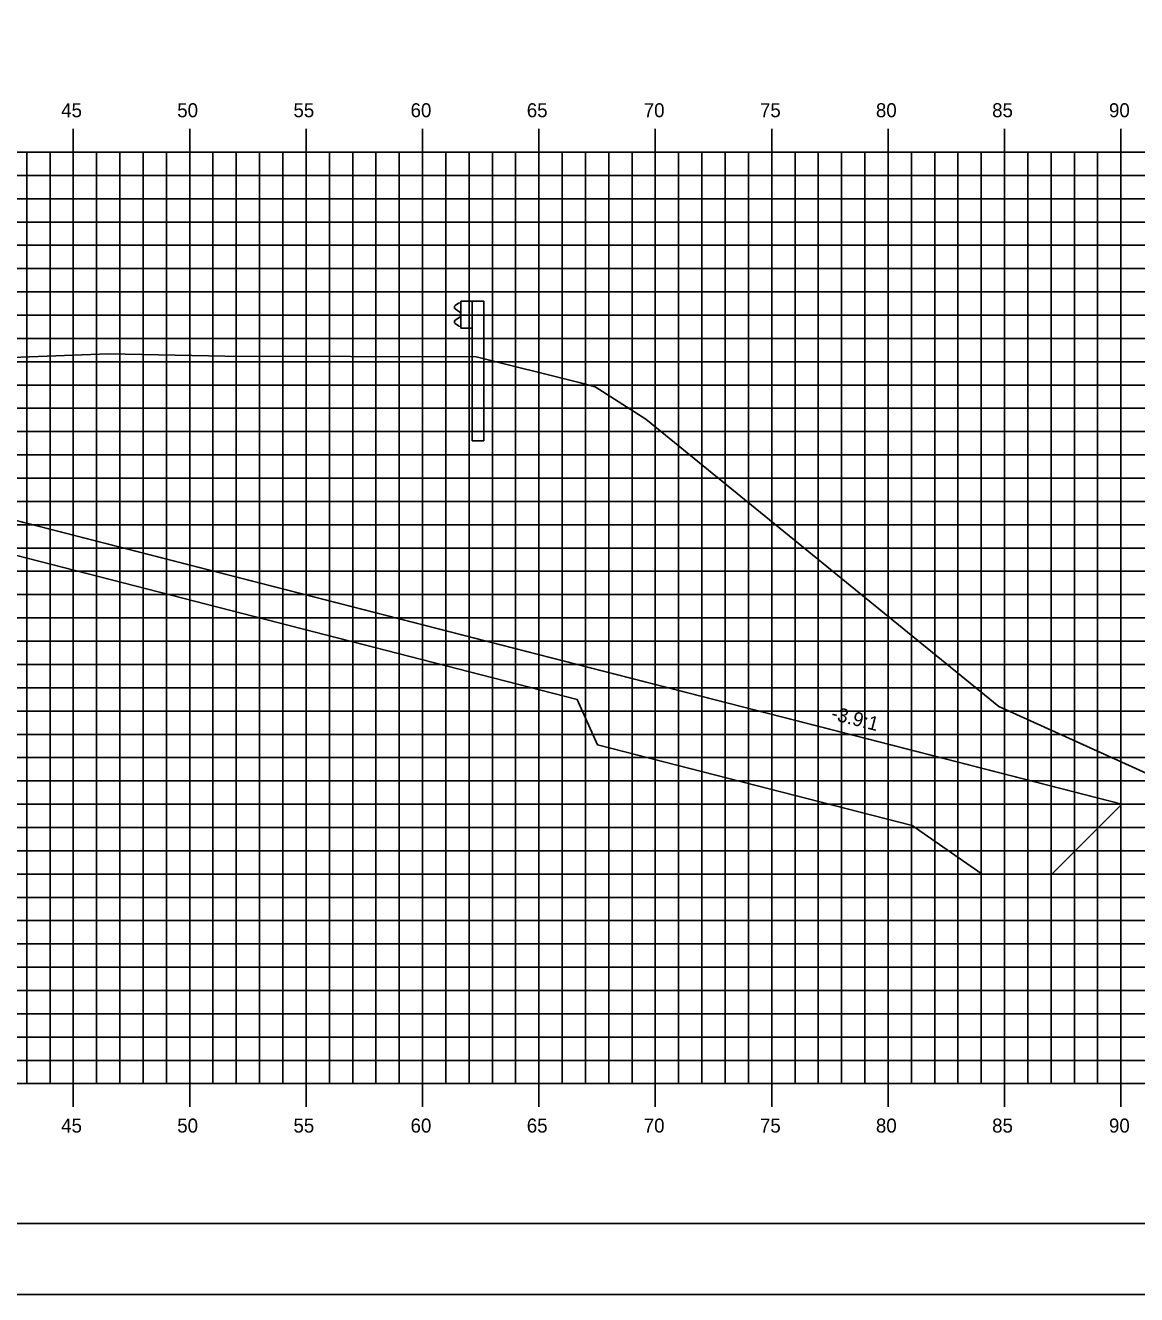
# Model space of a CAD drawing. Extents: x 850598 to 870284, y 366541 to 366651.
# Drawn here: x 853354.9 to 853402.6, y 366541.2 to 366595.7 of the extents above; entities that cross this region are included whole.
import ezdxf

# ---------------------------------------------------------------- set-up
doc = ezdxf.new("R2010")
doc.units = 0
for name, color, linetype in [('ANNOTATION', 7, 'Continuous'), ('BORDER', 7, 'Continuous'), ('D_Drainage_RipRap', 7, 'Continuous'), ('D_Roadway_Centerline', 7, 'Continuous'), ('D_Roadway_SlopeLines', 7, 'Continuous'), ('H_V ANNOTATION', 7, 'Continuous'), ('MAJOR', 7, 'Continuous'), ('MINOR', 7, 'Continuous'), ('PLOT BOUNDARY', 7, 'Continuous'), ('S_Guardrail_Beam', 7, 'Continuous'), ('S_Roadway_Centerline', 7, 'Continuous')]:
    doc.layers.add(name, color=color, linetype=linetype)

msp = doc.modelspace()

# ---------------------------------------------------------------- linework, layer by layer
at = {"layer": 'BORDER'}
msp.add_line((853266.976, 366544.225), (853426.976, 366544.225), dxfattribs=at)
at = {"layer": 'D_Drainage_RipRap'}
msp.add_lwpolyline([(853378.624, 366568.225), (853392.147, 366564.756), (853402.009, 366562.225), (853399.009, 366559.225), (853396.009, 366559.225), (853393.009, 366561.306), (853379.486, 366564.775), (853378.624, 366566.725), (853334.975, 366577.924), (853334.975, 366579.424)], close=True, dxfattribs=at)
at = {"layer": 'D_Roadway_Centerline'}
msp.add_lwpolyline([(853275.109, 366582.924), (853276.109, 366582.958), (853277.109, 366582.839), (853278.109, 366582.568), (853286.975, 366578.211), (853290.778, 366579.478), (853296.975, 366581.544), (853300.975, 366581.784), (853311.975, 366582.114), (853322.975, 366581.784), (853326.975, 366581.544), (853328.975, 366581.424), (853334.975, 366579.424), (853378.624, 366568.225), (853392.147, 366564.756), (853402.009, 366562.225), (853406.009, 366562.225)], dxfattribs=at)
at = {"layer": 'D_Roadway_SlopeLines'}
msp.add_lwpolyline([(853334.975, 366579.424), (853402.009, 366562.225), (853402.009, 366562.225)], dxfattribs=at)
at = {"layer": 'MAJOR'}
for p, q in [((853356.975, 366591.227), (853356.975, 366590.225)), ((853356.975, 366591.227), (853356.975, 366590.225)), ((853361.975, 366591.227), (853361.975, 366590.225)), ((853361.975, 366591.227), (853361.975, 366590.225)), ((853366.975, 366591.227), (853366.975, 366590.225)), ((853366.975, 366591.227), (853366.975, 366590.225)), ((853371.975, 366591.227), (853371.975, 366590.225)), ((853371.975, 366591.227), (853371.975, 366590.225)), ((853376.975, 366591.227), (853376.975, 366590.225)), ((853376.975, 366591.227), (853376.975, 366590.225)), ((853381.975, 366591.227), (853381.975, 366590.225)), ((853381.975, 366591.227), (853381.975, 366590.225)), ((853386.975, 366591.227), (853386.975, 366590.225)), ((853386.975, 366591.227), (853386.975, 366590.225)), ((853391.975, 366591.227), (853391.975, 366590.225)), ((853391.975, 366591.227), (853391.975, 366590.225)), ((853396.975, 366591.227), (853396.975, 366590.225)), ((853396.975, 366591.227), (853396.975, 366590.225)), ((853401.975, 366591.227), (853401.975, 366590.225)), ((853401.975, 366591.227), (853401.975, 366590.225)), ((853271.975, 366590.225), (853411.975, 366590.225)), ((853271.975, 366590.225), (853411.975, 366590.225)), ((853271.975, 366590.225), (853411.975, 366590.225)), ((853271.975, 366590.225), (853411.975, 366590.225)), ((853356.975, 366550.225), (853356.975, 366590.225)), ((853356.975, 366550.225), (853356.975, 366590.225)), ((853361.975, 366550.225), (853361.975, 366590.225)), ((853361.975, 366550.225), (853361.975, 366590.225)), ((853366.975, 366550.225), (853366.975, 366590.225)), ((853366.975, 366550.225), (853366.975, 366590.225)), ((853371.975, 366550.225), (853371.975, 366590.225)), ((853371.975, 366550.225), (853371.975, 366590.225)), ((853376.975, 366550.225), (853376.975, 366590.225)), ((853376.975, 366550.225), (853376.975, 366590.225)), ((853381.975, 366550.225), (853381.975, 366590.225)), ((853381.975, 366550.225), (853381.975, 366590.225)), ((853386.975, 366550.225), (853386.975, 366590.225)), ((853386.975, 366550.225), (853386.975, 366590.225)), ((853391.975, 366550.225), (853391.975, 366590.225)), ((853391.975, 366550.225), (853391.975, 366590.225)), ((853396.975, 366550.225), (853396.975, 366590.225)), ((853396.975, 366550.225), (853396.975, 366590.225)), ((853401.975, 366550.225), (853401.975, 366590.225)), ((853401.975, 366550.225), (853401.975, 366590.225)), ((853271.975, 366585.225), (853411.975, 366585.225)), ((853271.975, 366585.225), (853411.975, 366585.225)), ((853271.975, 366580.225), (853411.975, 366580.225)), ((853271.975, 366580.225), (853411.975, 366580.225)), ((853271.975, 366575.225), (853411.975, 366575.225)), ((853271.975, 366575.225), (853411.975, 366575.225)), ((853271.975, 366570.225), (853411.975, 366570.225)), ((853271.975, 366570.225), (853411.975, 366570.225)), ((853271.975, 366565.225), (853411.975, 366565.225)), ((853271.975, 366565.225), (853411.975, 366565.225)), ((853271.975, 366560.225), (853411.975, 366560.225)), ((853271.975, 366560.225), (853411.975, 366560.225)), ((853271.975, 366555.225), (853411.975, 366555.225)), ((853271.975, 366555.225), (853411.975, 366555.225)), ((853271.975, 366550.225), (853411.975, 366550.225)), ((853271.975, 366550.225), (853411.975, 366550.225)), ((853271.975, 366550.225), (853411.975, 366550.225)), ((853271.975, 366550.225), (853411.975, 366550.225)), ((853356.975, 366549.223), (853356.975, 366550.225)), ((853356.975, 366549.223), (853356.975, 366550.225)), ((853361.975, 366549.223), (853361.975, 366550.225)), ((853361.975, 366549.223), (853361.975, 366550.225)), ((853366.975, 366549.223), (853366.975, 366550.225)), ((853366.975, 366549.223), (853366.975, 366550.225)), ((853371.975, 366549.223), (853371.975, 366550.225)), ((853371.975, 366549.223), (853371.975, 366550.225)), ((853376.975, 366549.223), (853376.975, 366550.225)), ((853376.975, 366549.223), (853376.975, 366550.225)), ((853381.975, 366549.223), (853381.975, 366550.225)), ((853381.975, 366549.223), (853381.975, 366550.225)), ((853386.975, 366549.223), (853386.975, 366550.225)), ((853386.975, 366549.223), (853386.975, 366550.225)), ((853391.975, 366549.223), (853391.975, 366550.225)), ((853391.975, 366549.223), (853391.975, 366550.225)), ((853396.975, 366549.223), (853396.975, 366550.225)), ((853396.975, 366549.223), (853396.975, 366550.225)), ((853401.975, 366549.223), (853401.975, 366550.225)), ((853401.975, 366549.223), (853401.975, 366550.225))]:
    msp.add_line(p, q, dxfattribs=at)
at = {"layer": 'MINOR'}
for p, q in [((853354.975, 366550.225), (853354.975, 366590.225)), ((853354.975, 366550.225), (853354.975, 366590.225)), ((853355.975, 366550.225), (853355.975, 366590.225)), ((853355.975, 366550.225), (853355.975, 366590.225)), ((853357.975, 366550.225), (853357.975, 366590.225)), ((853357.975, 366550.225), (853357.975, 366590.225)), ((853358.975, 366550.225), (853358.975, 366590.225)), ((853358.975, 366550.225), (853358.975, 366590.225)), ((853359.975, 366550.225), (853359.975, 366590.225)), ((853359.975, 366550.225), (853359.975, 366590.225)), ((853360.975, 366550.225), (853360.975, 366590.225)), ((853360.975, 366550.225), (853360.975, 366590.225)), ((853362.975, 366550.225), (853362.975, 366590.225)), ((853362.975, 366550.225), (853362.975, 366590.225)), ((853363.975, 366550.225), (853363.975, 366590.225)), ((853363.975, 366550.225), (853363.975, 366590.225)), ((853364.975, 366550.225), (853364.975, 366590.225)), ((853364.975, 366550.225), (853364.975, 366590.225)), ((853365.975, 366550.225), (853365.975, 366590.225)), ((853365.975, 366550.225), (853365.975, 366590.225)), ((853367.975, 366550.225), (853367.975, 366590.225)), ((853367.975, 366550.225), (853367.975, 366590.225)), ((853368.975, 366550.225), (853368.975, 366590.225)), ((853368.975, 366550.225), (853368.975, 366590.225)), ((853369.975, 366550.225), (853369.975, 366590.225)), ((853369.975, 366550.225), (853369.975, 366590.225)), ((853370.975, 366550.225), (853370.975, 366590.225)), ((853370.975, 366550.225), (853370.975, 366590.225)), ((853372.975, 366550.225), (853372.975, 366590.225)), ((853372.975, 366550.225), (853372.975, 366590.225)), ((853373.975, 366550.225), (853373.975, 366590.225)), ((853373.975, 366550.225), (853373.975, 366590.225)), ((853374.975, 366550.225), (853374.975, 366590.225)), ((853374.975, 366550.225), (853374.975, 366590.225)), ((853375.975, 366550.225), (853375.975, 366590.225)), ((853375.975, 366550.225), (853375.975, 366590.225)), ((853377.975, 366550.225), (853377.975, 366590.225)), ((853377.975, 366550.225), (853377.975, 366590.225)), ((853378.975, 366550.225), (853378.975, 366590.225)), ((853378.975, 366550.225), (853378.975, 366590.225)), ((853379.975, 366550.225), (853379.975, 366590.225)), ((853379.975, 366550.225), (853379.975, 366590.225)), ((853380.975, 366550.225), (853380.975, 366590.225)), ((853380.975, 366550.225), (853380.975, 366590.225)), ((853382.975, 366550.225), (853382.975, 366590.225)), ((853382.975, 366550.225), (853382.975, 366590.225)), ((853383.975, 366550.225), (853383.975, 366590.225)), ((853383.975, 366550.225), (853383.975, 366590.225)), ((853384.975, 366550.225), (853384.975, 366590.225)), ((853384.975, 366550.225), (853384.975, 366590.225)), ((853385.975, 366550.225), (853385.975, 366590.225)), ((853385.975, 366550.225), (853385.975, 366590.225)), ((853387.975, 366550.225), (853387.975, 366590.225)), ((853387.975, 366550.225), (853387.975, 366590.225)), ((853388.975, 366550.225), (853388.975, 366590.225)), ((853388.975, 366550.225), (853388.975, 366590.225)), ((853389.975, 366550.225), (853389.975, 366590.225)), ((853389.975, 366550.225), (853389.975, 366590.225)), ((853390.975, 366550.225), (853390.975, 366590.225)), ((853390.975, 366550.225), (853390.975, 366590.225)), ((853392.975, 366550.225), (853392.975, 366590.225)), ((853392.975, 366550.225), (853392.975, 366590.225)), ((853393.975, 366550.225), (853393.975, 366590.225)), ((853393.975, 366550.225), (853393.975, 366590.225)), ((853394.975, 366550.225), (853394.975, 366590.225)), ((853394.975, 366550.225), (853394.975, 366590.225)), ((853395.975, 366550.225), (853395.975, 366590.225)), ((853395.975, 366550.225), (853395.975, 366590.225)), ((853397.975, 366550.225), (853397.975, 366590.225)), ((853397.975, 366550.225), (853397.975, 366590.225)), ((853398.975, 366550.225), (853398.975, 366590.225)), ((853398.975, 366550.225), (853398.975, 366590.225)), ((853399.975, 366550.225), (853399.975, 366590.225)), ((853399.975, 366550.225), (853399.975, 366590.225)), ((853400.975, 366550.225), (853400.975, 366590.225)), ((853400.975, 366550.225), (853400.975, 366590.225)), ((853271.975, 366589.225), (853411.975, 366589.225)), ((853271.975, 366589.225), (853411.975, 366589.225)), ((853271.975, 366588.225), (853411.975, 366588.225)), ((853271.975, 366588.225), (853411.975, 366588.225)), ((853271.975, 366587.225), (853411.975, 366587.225)), ((853271.975, 366587.225), (853411.975, 366587.225)), ((853271.975, 366586.225), (853411.975, 366586.225)), ((853271.975, 366586.225), (853411.975, 366586.225)), ((853271.975, 366584.225), (853411.975, 366584.225)), ((853271.975, 366584.225), (853411.975, 366584.225)), ((853271.975, 366583.225), (853411.975, 366583.225)), ((853271.975, 366583.225), (853411.975, 366583.225)), ((853271.975, 366582.225), (853411.975, 366582.225)), ((853271.975, 366582.225), (853411.975, 366582.225)), ((853271.975, 366581.225), (853411.975, 366581.225)), ((853271.975, 366581.225), (853411.975, 366581.225)), ((853271.975, 366579.225), (853411.975, 366579.225)), ((853271.975, 366579.225), (853411.975, 366579.225)), ((853271.975, 366578.225), (853411.975, 366578.225)), ((853271.975, 366578.225), (853411.975, 366578.225)), ((853271.975, 366577.225), (853411.975, 366577.225)), ((853271.975, 366577.225), (853411.975, 366577.225)), ((853271.975, 366576.225), (853411.975, 366576.225)), ((853271.975, 366576.225), (853411.975, 366576.225)), ((853271.975, 366574.225), (853411.975, 366574.225)), ((853271.975, 366574.225), (853411.975, 366574.225)), ((853271.975, 366573.225), (853411.975, 366573.225)), ((853271.975, 366573.225), (853411.975, 366573.225)), ((853271.975, 366572.225), (853411.975, 366572.225)), ((853271.975, 366572.225), (853411.975, 366572.225)), ((853271.975, 366571.225), (853411.975, 366571.225)), ((853271.975, 366571.225), (853411.975, 366571.225)), ((853271.975, 366569.225), (853411.975, 366569.225)), ((853271.975, 366569.225), (853411.975, 366569.225)), ((853271.975, 366568.225), (853411.975, 366568.225)), ((853271.975, 366568.225), (853411.975, 366568.225)), ((853271.975, 366567.225), (853411.975, 366567.225)), ((853271.975, 366567.225), (853411.975, 366567.225)), ((853271.975, 366566.225), (853411.975, 366566.225)), ((853271.975, 366566.225), (853411.975, 366566.225)), ((853271.975, 366564.225), (853411.975, 366564.225)), ((853271.975, 366564.225), (853411.975, 366564.225)), ((853271.975, 366563.225), (853411.975, 366563.225)), ((853271.975, 366563.225), (853411.975, 366563.225)), ((853271.975, 366562.225), (853411.975, 366562.225)), ((853271.975, 366562.225), (853411.975, 366562.225)), ((853271.975, 366561.225), (853411.975, 366561.225)), ((853271.975, 366561.225), (853411.975, 366561.225)), ((853271.975, 366559.225), (853411.975, 366559.225)), ((853271.975, 366559.225), (853411.975, 366559.225)), ((853271.975, 366558.225), (853411.975, 366558.225)), ((853271.975, 366558.225), (853411.975, 366558.225)), ((853271.975, 366557.225), (853411.975, 366557.225)), ((853271.975, 366557.225), (853411.975, 366557.225)), ((853271.975, 366556.225), (853411.975, 366556.225)), ((853271.975, 366556.225), (853411.975, 366556.225)), ((853271.975, 366554.225), (853411.975, 366554.225)), ((853271.975, 366554.225), (853411.975, 366554.225)), ((853271.975, 366553.225), (853411.975, 366553.225)), ((853271.975, 366553.225), (853411.975, 366553.225)), ((853271.975, 366552.225), (853411.975, 366552.225)), ((853271.975, 366552.225), (853411.975, 366552.225)), ((853271.975, 366551.225), (853411.975, 366551.225)), ((853271.975, 366551.225), (853411.975, 366551.225))]:
    msp.add_line(p, q, dxfattribs=at)
at = {"layer": 'PLOT BOUNDARY'}
msp.add_lwpolyline([(853258.882, 366541.166), (853428.882, 366541.166), (853428.882, 366651.166), (853258.882, 366651.166)], close=True, dxfattribs=at)
at = {"layer": 'S_Guardrail_Beam'}
for p, q in [((853373.525, 366583.738), (853373.381, 366583.638)), ((853373.624, 366583.76), (853373.542, 366583.745)), ((853373.624, 366583.833), (853374.113, 366583.833)), ((853373.624, 366582.666), (853373.624, 366583.833)), ((853374.113, 366583.833), (853374.605, 366583.833)), ((853374.113, 366583.833), (853374.113, 366582.666)), ((853374.605, 366583.833), (853374.605, 366577.833)), ((853373.381, 366583.495), (853373.577, 366583.359)), ((853373.61, 366583.295), (853373.61, 366583.204)), ((853373.577, 366583.139), (853373.381, 366583.003)), ((853373.381, 366582.86), (853373.525, 366582.76)), ((853373.542, 366582.753), (853373.624, 366582.739)), ((853374.113, 366582.666), (853373.624, 366582.666)), ((853374.113, 366577.833), (853374.113, 366582.666)), ((853374.113, 366577.833), (853374.605, 366577.833))]:
    msp.add_line(p, q, dxfattribs=at)
for centre, major_axis, start_param, end_param in [((853373.549, 366583.704), (-0.0417, 0), 4.886922, 5.323254), ((853373.432, 366583.567), (-0.0877, 0), 5.323254, 7.243116), ((853373.531, 366583.295), (0.0789, 0), 0, 0.959931), ((853373.531, 366583.204), (0.0789, 0), 5.323254, 6.283185), ((853373.432, 366582.932), (-0.0877, 0), 5.323254, 7.243116), ((853373.549, 366582.794), (-0.0417, 0), 0.959931, 1.396263)]:
    msp.add_ellipse(centre, major_axis=major_axis, ratio=0.995501, start_param=start_param, end_param=end_param, dxfattribs=at)
at = {"layer": 'S_Roadway_Centerline'}
msp.add_lwpolyline([(853348.29, 366581.184), (853358.483, 366581.563), (853363.499, 366581.464), (853374.278, 366581.442), (853378.703, 366580.336), (853379.39, 366580.145), (853381.562, 366578.755), (853396.732, 366566.418), (853411.975, 366559.528)], dxfattribs=at)

# ---------------------------------------------------------------- texts
at = {"layer": 'ANNOTATION'}
msp.add_text('-3.9:1', height=0.6, rotation=345.6098, dxfattribs=at).set_placement((853389.49, 366565.87))
at = {"layer": 'H_V ANNOTATION'}
for s, p in [('45', (853356.454, 366591.725)), ('50', (853361.44, 366591.725)), ('55', (853366.432, 366591.725)), ('60', (853371.462, 366591.725)), ('65', (853376.454, 366591.725)), ('70', (853381.478, 366591.725)), ('75', (853386.47, 366591.725)), ('80', (853391.451, 366591.725)), ('85', (853396.443, 366591.725)), ('90', (853401.462, 366591.725)), ('45', (853356.454, 366548.125)), ('50', (853361.44, 366548.125)), ('55', (853366.432, 366548.125)), ('60', (853371.462, 366548.125)), ('65', (853376.454, 366548.125)), ('70', (853381.478, 366548.125)), ('75', (853386.47, 366548.125)), ('80', (853391.451, 366548.125)), ('85', (853396.443, 366548.125)), ('90', (853401.462, 366548.125))]:
    msp.add_text(s, height=0.6, dxfattribs=at).set_placement(p)
at = {"layer": 'S_Roadway_Centerline'}
for s, p in [('C', (853358.477, 366581.563)), ('L', (853358.483, 366581.555))]:
    msp.add_text(s, height=0.0146, dxfattribs=at).set_placement(p)

doc.saveas('drawing.dxf')
